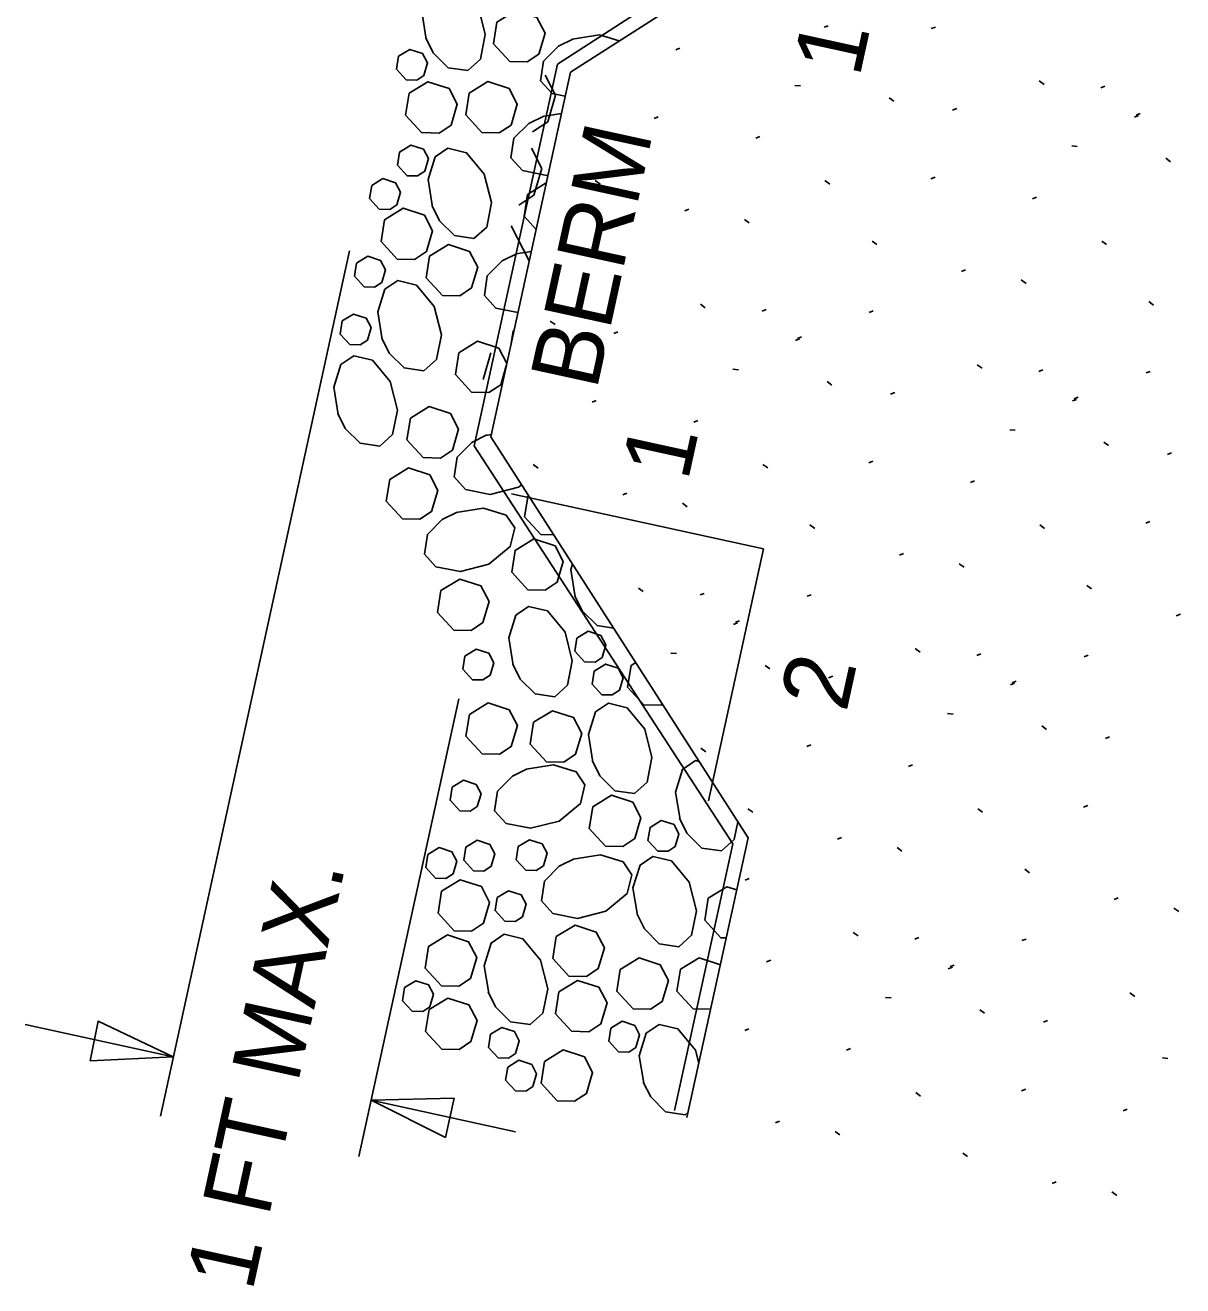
# Model space of a CAD drawing. Extents: x 2126110 to 2128246, y 1804858 to 1811658.
# Drawn here: x 2126534.8 to 2126619.6, y 1805336.1 to 1805428.3 of the extents above; entities that cross this region are included whole.
import ezdxf

# ---------------------------------------------------------------- set-up
doc = ezdxf.new("R2010")
doc.units = 0
doc.layers.add('1', color=7, linetype='Continuous')

msp = doc.modelspace()

# ---------------------------------------------------------------- linework, layer by layer
at = {"layer": '1'}
for p, q in [((2126573.804, 1805425.496), (2126651.738, 1805475.782)), ((2126574.757, 1805424.895), (2126652.954, 1805475.045)), ((2126593.323, 1805428.191), (2126593.622, 1805428.308)), ((2126601.172, 1805428.09), (2126601.47, 1805428.207)), ((2126582.473, 1805426.545), (2126582.771, 1805426.662)), ((2126595.778, 1805426.038), (2126596.076, 1805426.155)), ((2126595.915, 1805426.19), (2126596.213, 1805426.307)), ((2126567.699, 1805397.559), (2126573.804, 1805425.496)), ((2126574.757, 1805424.895), (2126568.927, 1805398.216)), ((2126572.902, 1805424.696), (2126573.665, 1805423.227)), ((2126609.429, 1805424.01), (2126609.077, 1805424.269)), ((2126573.665, 1805423.227), (2126573.087, 1805421.269)), ((2126591.189, 1805423.939), (2126591.589, 1805423.897)), ((2126613.586, 1805423.763), (2126613.884, 1805423.88)), ((2126598.434, 1805422.776), (2126598.082, 1805423.035)), ((2126572.713, 1805421.663), (2126574.101, 1805421.89)), ((2126580.884, 1805421.521), (2126581.182, 1805421.638)), ((2126602.736, 1805422.117), (2126603.034, 1805422.234)), ((2126616.04, 1805421.611), (2126616.339, 1805421.727)), ((2126616.177, 1805421.763), (2126616.476, 1805421.879)), ((2126573.087, 1805421.269), (2126571.976, 1805420.532)), ((2126588.32, 1805420.067), (2126588.618, 1805420.183)), ((2126611.451, 1805419.511), (2126611.851, 1805419.47)), ((2126571.898, 1805419.333), (2126572.661, 1805417.864)), ((2126618.697, 1805418.348), (2126618.344, 1805418.607)), ((2126572.661, 1805417.864), (2126572.082, 1805415.906)), ((2126576.923, 1805416.706), (2126576.57, 1805416.964)), ((2126593.74, 1805416.712), (2126593.387, 1805416.971)), ((2126601.146, 1805417.093), (2126601.444, 1805417.21)), ((2126572.082, 1805415.906), (2126570.972, 1805415.169)), ((2126608.583, 1805415.639), (2126608.881, 1805415.756)), ((2126583.123, 1805414.747), (2126583.421, 1805414.863)), ((2126587.846, 1805413.864), (2126587.493, 1805414.123)), ((2126570.403, 1805413.663), (2126571.74, 1805411.087)), ((2126597.185, 1805412.278), (2126596.833, 1805412.537)), ((2126614.002, 1805412.284), (2126613.65, 1805412.543)), ((2126558.575, 1805411.836), (2126544.731, 1805348.483)), ((2126570.763, 1805411.597), (2126571.892, 1805411.783)), ((2126576.369, 1805411.739), (2126576.667, 1805411.856)), ((2126603.385, 1805410.319), (2126603.684, 1805410.436)), ((2126608.108, 1805409.436), (2126607.756, 1805409.695)), ((2126584.626, 1805407.66), (2126584.274, 1805407.918)), ((2126588.783, 1805407.413), (2126589.081, 1805407.529)), ((2126617.448, 1805407.85), (2126617.095, 1805408.109)), ((2126573.631, 1805406.426), (2126573.279, 1805406.684)), ((2126596.631, 1805407.312), (2126596.929, 1805407.428)), ((2126577.933, 1805405.767), (2126578.231, 1805405.883)), ((2126591.237, 1805405.26), (2126591.536, 1805405.377)), ((2126591.374, 1805405.412), (2126591.673, 1805405.529)), ((2126568.932, 1805404.359), (2126568.354, 1805402.401)), ((2126586.648, 1805403.161), (2126587.048, 1805403.119)), ((2126604.889, 1805403.232), (2126604.536, 1805403.491)), ((2126609.045, 1805402.985), (2126609.344, 1805403.102)), ((2126616.894, 1805402.884), (2126617.192, 1805403.001)), ((2126593.894, 1805401.998), (2126593.541, 1805402.257)), ((2126598.195, 1805401.339), (2126598.493, 1805401.455)), ((2126611.637, 1805400.984), (2126611.935, 1805401.101)), ((2126576.343, 1805400.743), (2126576.641, 1805400.859)), ((2126611.5, 1805400.832), (2126611.798, 1805400.949)), ((2126583.78, 1805399.288), (2126584.078, 1805399.405)), ((2126568.547, 1805398.311), (2126568.963, 1805398.38)), ((2126606.911, 1805398.733), (2126607.311, 1805398.691)), ((2126586.642, 1805368.411), (2126567.699, 1805397.559)), ((2126568.927, 1805398.216), (2126587.758, 1805368.854)), ((2126614.156, 1805397.57), (2126613.804, 1805397.829)), ((2126596.606, 1805396.315), (2126596.904, 1805396.432)), ((2126618.458, 1805396.911), (2126618.756, 1805397.028)), ((2126572.382, 1805395.927), (2126572.03, 1805396.186)), ((2126589.199, 1805395.934), (2126588.847, 1805396.192)), ((2126604.042, 1805394.861), (2126604.341, 1805394.977)), ((2126570.435, 1805394.037), (2126588.886, 1805390.005)), ((2126578.582, 1805393.968), (2126578.881, 1805394.085)), ((2126583.305, 1805393.086), (2126582.953, 1805393.345)), ((2126616.868, 1805391.887), (2126617.167, 1805392.004)), ((2126573.536, 1805391.03), (2126572.584, 1805391.051)), ((2126592.645, 1805391.499), (2126592.292, 1805391.758)), ((2126609.462, 1805391.506), (2126609.11, 1805391.765)), ((2126588.886, 1805390.005), (2126584.857, 1805371.568)), ((2126598.845, 1805389.541), (2126599.143, 1805389.657)), ((2126603.568, 1805388.658), (2126603.215, 1805388.917)), ((2126612.907, 1805387.072), (2126612.555, 1805387.331)), ((2126580.086, 1805386.881), (2126579.733, 1805387.14)), ((2126584.242, 1805386.634), (2126584.541, 1805386.751)), ((2126592.091, 1805386.533), (2126592.389, 1805386.65)), ((2126586.697, 1805384.482), (2126586.995, 1805384.598)), ((2126586.834, 1805384.634), (2126587.132, 1805384.75)), ((2126619.107, 1805385.113), (2126619.406, 1805385.23)), ((2126600.349, 1805382.453), (2126599.996, 1805382.712)), ((2126582.108, 1805382.382), (2126582.508, 1805382.34)), ((2126604.505, 1805382.207), (2126604.803, 1805382.323)), ((2126612.353, 1805382.106), (2126612.652, 1805382.222)), ((2126589.353, 1805381.219), (2126589.001, 1805381.478)), ((2126593.655, 1805380.56), (2126593.953, 1805380.677)), ((2126606.96, 1805380.054), (2126607.258, 1805380.171)), ((2126607.096, 1805380.206), (2126607.395, 1805380.322)), ((2126566.577, 1805379.04), (2126559.253, 1805345.524)), ((2126602.37, 1805377.955), (2126602.77, 1805377.913)), ((2126609.616, 1805376.792), (2126609.263, 1805377.05)), ((2126613.917, 1805376.133), (2126614.216, 1805376.249)), ((2126584.659, 1805375.155), (2126584.306, 1805375.414)), ((2126592.065, 1805375.537), (2126592.363, 1805375.653)), ((2126599.502, 1805374.082), (2126599.8, 1805374.199)), ((2126588.104, 1805370.721), (2126587.752, 1805370.98)), ((2126604.922, 1805370.727), (2126604.569, 1805370.986)), ((2126612.328, 1805371.109), (2126612.626, 1805371.225)), ((2126583.282, 1805348.371), (2126587.758, 1805368.854)), ((2126594.304, 1805368.762), (2126594.603, 1805368.879)), ((2126582.374, 1805348.883), (2126586.642, 1805368.411)), ((2126599.027, 1805367.88), (2126598.675, 1805368.138)), ((2126608.367, 1805366.293), (2126608.014, 1805366.552)), ((2126587.55, 1805365.755), (2126587.848, 1805365.872)), ((2126614.567, 1805364.334), (2126614.865, 1805364.451)), ((2126619.29, 1805363.452), (2126618.937, 1805363.711)), ((2126586.159, 1805361.535), (2126585.771, 1805361.544)), ((2126595.808, 1805361.675), (2126595.456, 1805361.934)), ((2126599.964, 1805361.428), (2126600.263, 1805361.545)), ((2126607.813, 1805361.327), (2126608.111, 1805361.444)), ((2126589.114, 1805359.782), (2126589.413, 1805359.899)), ((2126602.556, 1805359.427), (2126602.854, 1805359.544)), ((2126602.419, 1805359.275), (2126602.717, 1805359.392)), ((2126597.83, 1805357.176), (2126598.23, 1805357.134)), ((2126616.071, 1805357.247), (2126615.718, 1805357.506)), ((2126605.075, 1805356.013), (2126604.723, 1805356.272)), ((2126534.837, 1805355.185), (2126545.678, 1805352.816)), ((2126609.377, 1805355.354), (2126609.675, 1805355.471)), ((2126587.525, 1805354.758), (2126587.823, 1805354.875)), ((2126594.961, 1805353.304), (2126595.26, 1805353.42)), ((2126618.093, 1805352.748), (2126618.492, 1805352.707)), ((2126607.787, 1805350.33), (2126608.086, 1805350.447)), ((2126560.155, 1805349.652), (2126570.729, 1805347.342)), ((2126600.381, 1805349.949), (2126600.029, 1805350.208)), ((2126615.224, 1805348.876), (2126615.522, 1805348.993)), ((2126589.764, 1805347.984), (2126590.062, 1805348.1)), ((2126594.487, 1805347.101), (2126594.134, 1805347.36)), ((2126603.826, 1805345.515), (2126603.474, 1805345.774)), ((2126610.027, 1805343.556), (2126610.325, 1805343.673)), ((2126614.749, 1805342.673), (2126614.397, 1805342.932))]:
    msp.add_line(p, q, dxfattribs=at)
for points in [[(2126564.199, 1805427.33), (2126563.871, 1805429.333), (2126564.387, 1805430.994), (2126565.328, 1805431.631), (2126566.696, 1805431.306), (2126567.99, 1805429.744), (2126568.522, 1805427.65), (2126568.164, 1805425.864), (2126567.234, 1805425.019), (2126565.796, 1805425.233), (2126564.706, 1805426.323), (2126564.168, 1805427.415)], [(2126570.308, 1805425.684), (2126569.122, 1805426.974), (2126569.375, 1805428.567), (2126570.748, 1805429.413), (2126572.302, 1805428.907), (2126572.898, 1805427.759), (2126572.446, 1805426.231), (2126571.578, 1805425.655), (2126570.309, 1805425.684)], [(2126574.376, 1805423.151), (2126573.417, 1805423.343), (2126572.571, 1805424.273), (2126572.786, 1805425.71), (2126573.875, 1805426.8), (2126574.968, 1805427.339)], [(2126574.883, 1805427.308), (2126576.886, 1805427.636), (2126578.331, 1805427.187)], [(2126562.736, 1805424.337), (2126562.024, 1805425.112), (2126562.176, 1805426.068), (2126563.001, 1805426.575), (2126563.932, 1805426.272), (2126564.29, 1805425.583), (2126564.019, 1805424.665), (2126563.498, 1805424.32), (2126562.736, 1805424.338)], [(2126563.875, 1805420.475), (2126562.688, 1805421.766), (2126562.942, 1805423.359), (2126564.315, 1805424.204), (2126565.869, 1805423.699), (2126566.465, 1805422.551), (2126566.013, 1805421.022), (2126565.145, 1805420.446), (2126563.875, 1805420.476)], [(2126568.273, 1805420.485), (2126567.086, 1805421.776), (2126567.341, 1805423.369), (2126568.713, 1805424.214), (2126570.267, 1805423.709), (2126570.863, 1805422.561), (2126570.411, 1805421.032), (2126569.543, 1805420.457), (2126568.273, 1805420.486)], [(2126573.111, 1805417.36), (2126573.032, 1805417.34), (2126571.247, 1805417.697), (2126570.401, 1805418.627), (2126570.616, 1805420.065), (2126571.705, 1805421.154), (2126572.797, 1805421.693)], [(2126562.806, 1805417.325), (2126562.094, 1805418.1), (2126562.246, 1805419.056), (2126563.071, 1805419.564), (2126564.002, 1805419.26), (2126564.36, 1805418.572), (2126564.089, 1805417.654), (2126563.568, 1805417.308), (2126562.806, 1805417.326)], [(2126564.658, 1805415.033), (2126564.33, 1805417.035), (2126564.846, 1805418.696), (2126565.787, 1805419.334), (2126567.155, 1805419.008), (2126568.449, 1805417.445), (2126568.98, 1805415.352), (2126568.623, 1805413.567), (2126567.693, 1805412.72), (2126566.255, 1805412.936), (2126565.166, 1805414.025), (2126564.627, 1805415.118)], [(2126560.761, 1805414.874), (2126560.05, 1805415.649), (2126560.202, 1805416.604), (2126561.026, 1805417.112), (2126561.958, 1805416.809), (2126562.315, 1805416.12), (2126562.044, 1805415.202), (2126561.524, 1805414.857), (2126560.762, 1805414.874)], [(2126572.243, 1805413.391), (2126571.358, 1805414.354), (2126571.612, 1805415.947), (2126572.985, 1805416.793), (2126572.987, 1805416.792)], [(2126562.076, 1805411.222), (2126560.89, 1805412.514), (2126561.143, 1805414.106), (2126562.516, 1805414.952), (2126564.07, 1805414.446), (2126564.666, 1805413.298), (2126564.214, 1805411.769), (2126563.346, 1805411.194), (2126562.076, 1805411.223)], [(2126565.378, 1805408.558), (2126564.192, 1805409.85), (2126564.446, 1805411.442), (2126565.819, 1805412.288), (2126567.373, 1805411.782), (2126567.969, 1805410.634), (2126567.516, 1805409.106), (2126566.648, 1805408.53), (2126565.379, 1805408.559)], [(2126559.659, 1805409.187), (2126558.947, 1805409.962), (2126559.099, 1805410.918), (2126559.923, 1805411.425), (2126560.855, 1805411.122), (2126561.213, 1805410.433), (2126560.942, 1805409.515), (2126560.421, 1805409.17), (2126559.659, 1805409.188)], [(2126570.914, 1805407.309), (2126569.297, 1805407.632), (2126568.452, 1805408.563), (2126568.667, 1805410), (2126569.756, 1805411.09), (2126570.848, 1805411.629)], [(2126560.98, 1805405.346), (2126560.652, 1805407.348), (2126561.168, 1805409.01), (2126562.109, 1805409.647), (2126563.477, 1805409.321), (2126564.772, 1805407.758), (2126565.303, 1805405.666), (2126564.945, 1805403.88), (2126564.015, 1805403.034), (2126562.578, 1805403.249), (2126561.488, 1805404.338), (2126560.949, 1805405.431)], [(2126558.605, 1805404.961), (2126557.894, 1805405.736), (2126558.046, 1805406.691), (2126558.87, 1805407.198), (2126559.802, 1805406.896), (2126560.16, 1805406.206), (2126559.889, 1805405.289), (2126559.367, 1805404.944), (2126558.606, 1805404.961)], [(2126570.421, 1805405.049), (2126570.566, 1805405.96), (2126570.628, 1805405.999)], [(2126567.514, 1805401.472), (2126566.328, 1805402.764), (2126566.582, 1805404.356), (2126567.955, 1805405.202), (2126569.509, 1805404.697), (2126570.096, 1805403.565)], [(2126557.76, 1805399.838), (2126557.432, 1805401.84), (2126557.948, 1805403.501), (2126558.889, 1805404.139), (2126560.257, 1805403.813), (2126561.552, 1805402.25), (2126562.083, 1805400.157), (2126561.725, 1805398.372), (2126560.795, 1805397.526), (2126559.358, 1805397.741), (2126558.268, 1805398.83), (2126557.729, 1805399.923)], [(2126570.059, 1805403.394), (2126569.653, 1805402.02), (2126568.784, 1805401.444), (2126567.514, 1805401.473)], [(2126563.971, 1805396.687), (2126562.786, 1805397.978), (2126563.039, 1805399.571), (2126564.412, 1805400.417), (2126565.966, 1805399.911), (2126566.562, 1805398.763), (2126566.11, 1805397.235), (2126565.242, 1805396.659), (2126563.972, 1805396.688)], [(2126571.181, 1805394.703), (2126570.96, 1805394.52), (2126568.866, 1805393.989), (2126567.081, 1805394.347), (2126566.235, 1805395.277), (2126566.45, 1805396.714), (2126567.539, 1805397.804), (2126568.632, 1805398.343)], [(2126562.454, 1805392.204), (2126561.267, 1805393.495), (2126561.522, 1805395.088), (2126562.894, 1805395.934), (2126564.448, 1805395.429), (2126565.044, 1805394.281), (2126564.592, 1805392.752), (2126563.724, 1805392.176), (2126562.454, 1805392.205)], [(2126572.584, 1805391.051), (2126571.397, 1805392.342), (2126571.651, 1805393.934), (2126571.667, 1805393.944)], [(2126566.377, 1805392.666), (2126568.379, 1805392.994), (2126570.041, 1805392.478), (2126570.678, 1805391.537), (2126570.352, 1805390.169), (2126568.79, 1805388.875), (2126566.696, 1805388.344), (2126564.911, 1805388.701), (2126564.065, 1805389.631), (2126564.28, 1805391.069), (2126565.368, 1805392.158), (2126566.461, 1805392.697)], [(2126571.638, 1805387.011), (2126570.452, 1805388.302), (2126570.706, 1805389.895), (2126572.078, 1805390.74), (2126573.632, 1805390.235), (2126574.228, 1805389.087), (2126573.777, 1805387.559), (2126572.909, 1805386.983), (2126571.639, 1805387.012)], [(2126575.107, 1805386.486), (2126574.779, 1805388.489), (2126574.906, 1805388.895)], [(2126566.208, 1805384.067), (2126565.022, 1805385.358), (2126565.276, 1805386.95), (2126566.649, 1805387.797), (2126568.203, 1805387.291), (2126568.798, 1805386.143), (2126568.347, 1805384.614), (2126567.479, 1805384.039), (2126566.208, 1805384.067)], [(2126577.911, 1805384.209), (2126576.705, 1805384.389), (2126575.615, 1805385.478), (2126575.076, 1805386.571)], [(2126570.566, 1805381.488), (2126570.238, 1805383.49), (2126570.754, 1805385.151), (2126571.695, 1805385.789), (2126573.063, 1805385.463), (2126574.357, 1805383.9), (2126574.888, 1805381.807), (2126574.531, 1805380.022), (2126573.601, 1805379.175), (2126572.163, 1805379.391), (2126571.074, 1805380.48), (2126570.535, 1805381.572)], [(2126575.793, 1805381.735), (2126575.081, 1805382.51), (2126575.234, 1805383.466), (2126576.057, 1805383.973), (2126576.99, 1805383.67), (2126577.347, 1805382.981), (2126577.076, 1805382.063), (2126576.556, 1805381.718), (2126575.793, 1805381.736)], [(2126567.584, 1805380.429), (2126566.872, 1805381.203), (2126567.024, 1805382.159), (2126567.848, 1805382.666), (2126568.78, 1805382.363), (2126569.138, 1805381.675), (2126568.867, 1805380.757), (2126568.346, 1805380.411), (2126567.584, 1805380.429)], [(2126580.124, 1805378.59), (2126578.938, 1805379.882), (2126579.192, 1805381.474), (2126579.53, 1805381.683)], [(2126577.058, 1805379.329), (2126576.346, 1805380.104), (2126576.499, 1805381.059), (2126577.322, 1805381.567), (2126578.255, 1805381.264), (2126578.613, 1805380.575), (2126578.342, 1805379.657), (2126577.821, 1805379.312), (2126577.059, 1805379.33)], [(2126568.285, 1805374.996), (2126567.099, 1805376.287), (2126567.353, 1805377.879), (2126568.725, 1805378.725), (2126570.28, 1805378.22), (2126570.876, 1805377.072), (2126570.423, 1805375.543), (2126569.555, 1805374.967), (2126568.286, 1805374.996)], [(2126572.991, 1805374.426), (2126571.805, 1805375.718), (2126572.06, 1805377.311), (2126573.432, 1805378.156), (2126574.986, 1805377.651), (2126575.582, 1805376.503), (2126575.13, 1805374.974), (2126574.262, 1805374.398), (2126572.992, 1805374.427)], [(2126576.4, 1805374.403), (2126576.073, 1805376.406), (2126576.589, 1805378.067), (2126577.53, 1805378.704), (2126578.898, 1805378.378), (2126580.192, 1805376.816), (2126580.723, 1805374.723), (2126580.366, 1805372.937), (2126579.436, 1805372.091), (2126577.998, 1805372.306), (2126576.909, 1805373.395), (2126576.37, 1805374.488)], [(2126581.491, 1805378.626), (2126581.394, 1805378.562), (2126580.125, 1805378.591)], [(2126582.778, 1805370.202), (2126582.451, 1805372.204), (2126582.966, 1805373.865), (2126583.907, 1805374.503), (2126584.177, 1805374.439)], [(2126571.512, 1805373.872), (2126573.514, 1805374.201), (2126575.175, 1805373.684), (2126575.813, 1805372.743), (2126575.487, 1805371.375), (2126573.924, 1805370.081), (2126571.831, 1805369.55), (2126570.046, 1805369.907), (2126569.2, 1805370.837), (2126569.415, 1805372.275), (2126570.504, 1805373.364), (2126571.597, 1805373.903)], [(2126566.654, 1805370.831), (2126565.942, 1805371.605), (2126566.095, 1805372.561), (2126566.919, 1805373.068), (2126567.85, 1805372.765), (2126568.208, 1805372.076), (2126567.937, 1805371.159), (2126567.416, 1805370.813), (2126566.654, 1805370.83)], [(2126577.32, 1805368.249), (2126576.133, 1805369.541), (2126576.388, 1805371.134), (2126577.76, 1805371.979), (2126579.314, 1805371.474), (2126579.91, 1805370.326), (2126579.458, 1805368.797), (2126578.59, 1805368.221), (2126577.32, 1805368.251)], [(2126581.141, 1805367.885), (2126580.429, 1805368.66), (2126580.582, 1805369.615), (2126581.405, 1805370.122), (2126582.338, 1805369.82), (2126582.696, 1805369.13), (2126582.425, 1805368.213), (2126581.903, 1805367.868), (2126581.142, 1805367.885)], [(2126587.003, 1805370.032), (2126586.743, 1805368.736), (2126585.813, 1805367.89), (2126584.376, 1805368.104), (2126583.286, 1805369.194), (2126582.747, 1805370.287)], [(2126564.875, 1805365.898), (2126564.164, 1805366.673), (2126564.316, 1805367.629), (2126565.14, 1805368.136), (2126566.072, 1805367.833), (2126566.43, 1805367.144), (2126566.159, 1805366.227), (2126565.638, 1805365.881), (2126564.876, 1805365.898)], [(2126567.659, 1805366.443), (2126566.948, 1805367.217), (2126567.1, 1805368.173), (2126567.924, 1805368.68), (2126568.856, 1805368.377), (2126569.214, 1805367.688), (2126568.943, 1805366.771), (2126568.422, 1805366.425), (2126567.66, 1805366.442)], [(2126571.491, 1805366.476), (2126570.779, 1805367.251), (2126570.931, 1805368.207), (2126571.756, 1805368.714), (2126572.687, 1805368.411), (2126573.045, 1805367.722), (2126572.774, 1805366.805), (2126572.253, 1805366.459), (2126571.492, 1805366.477)], [(2126574.942, 1805367.282), (2126576.945, 1805367.61), (2126578.606, 1805367.094), (2126579.244, 1805366.153), (2126578.918, 1805364.785), (2126577.355, 1805363.49), (2126575.262, 1805362.96), (2126573.477, 1805363.317), (2126572.63, 1805364.247), (2126572.846, 1805365.685), (2126573.934, 1805366.774), (2126575.027, 1805367.313)], [(2126579.661, 1805363.19), (2126579.333, 1805365.193), (2126579.849, 1805366.854), (2126580.79, 1805367.491), (2126582.158, 1805367.166), (2126583.453, 1805365.603), (2126583.984, 1805363.51), (2126583.626, 1805361.724), (2126582.696, 1805360.878), (2126581.259, 1805361.093), (2126580.169, 1805362.182), (2126579.63, 1805363.275)], [(2126566.248, 1805362.054), (2126565.061, 1805363.345), (2126565.315, 1805364.938), (2126566.688, 1805365.784), (2126568.242, 1805365.279), (2126568.838, 1805364.13), (2126568.386, 1805362.602), (2126567.517, 1805362.026), (2126566.248, 1805362.055)], [(2126585.77, 1805361.543), (2126584.584, 1805362.834), (2126584.838, 1805364.427), (2126586.21, 1805365.272), (2126586.925, 1805365.04)], [(2126569.95, 1805362.747), (2126569.238, 1805363.522), (2126569.39, 1805364.478), (2126570.214, 1805364.985), (2126571.147, 1805364.682), (2126571.505, 1805363.993), (2126571.233, 1805363.075), (2126570.712, 1805362.73), (2126569.95, 1805362.748)], [(2126574.648, 1805358.735), (2126573.461, 1805360.026), (2126573.715, 1805361.619), (2126575.088, 1805362.465), (2126576.642, 1805361.959), (2126577.238, 1805360.81), (2126576.786, 1805359.283), (2126575.918, 1805358.707), (2126574.648, 1805358.736)], [(2126565.302, 1805358.015), (2126564.116, 1805359.306), (2126564.37, 1805360.899), (2126565.742, 1805361.744), (2126567.296, 1805361.239), (2126567.892, 1805360.091), (2126567.441, 1805358.562), (2126566.573, 1805357.987), (2126565.303, 1805358.015)], [(2126568.771, 1805357.49), (2126568.443, 1805359.493), (2126568.96, 1805361.153), (2126569.9, 1805361.791), (2126571.269, 1805361.465), (2126572.563, 1805359.903), (2126573.094, 1805357.809), (2126572.737, 1805356.024), (2126571.806, 1805355.178), (2126570.369, 1805355.393), (2126569.279, 1805356.482), (2126568.74, 1805357.574)], [(2126579.337, 1805356.334), (2126578.15, 1805357.626), (2126578.405, 1805359.218), (2126579.777, 1805360.064), (2126581.331, 1805359.558), (2126581.927, 1805358.41), (2126581.475, 1805356.882), (2126580.607, 1805356.306), (2126579.337, 1805356.335)], [(2126583.735, 1805356.345), (2126582.548, 1805357.636), (2126582.803, 1805359.228), (2126584.175, 1805360.074), (2126585.729, 1805359.568), (2126585.729, 1805359.568)], [(2126563.174, 1805356.157), (2126562.462, 1805356.932), (2126562.614, 1805357.888), (2126563.438, 1805358.395), (2126564.371, 1805358.092), (2126564.728, 1805357.403), (2126564.457, 1805356.486), (2126563.936, 1805356.141), (2126563.174, 1805356.158)], [(2126574.84, 1805354.689), (2126573.655, 1805355.981), (2126573.908, 1805357.574), (2126575.281, 1805358.419), (2126576.835, 1805357.914), (2126577.431, 1805356.766), (2126576.979, 1805355.237), (2126576.111, 1805354.661), (2126574.841, 1805354.691)], [(2126565.333, 1805353.393), (2126564.146, 1805354.684), (2126564.401, 1805356.277), (2126565.773, 1805357.122), (2126567.327, 1805356.617), (2126567.923, 1805355.469), (2126567.472, 1805353.941), (2126566.603, 1805353.365), (2126565.334, 1805353.394)], [(2126585.021, 1805356.327), (2126585.005, 1805356.316), (2126583.735, 1805356.345)], [(2126569.457, 1805352.739), (2126568.745, 1805353.514), (2126568.898, 1805354.469), (2126569.721, 1805354.976), (2126570.654, 1805354.674), (2126571.011, 1805353.984), (2126570.74, 1805353.067), (2126570.219, 1805352.722), (2126569.457, 1805352.74)], [(2126578.268, 1805353.185), (2126577.557, 1805353.96), (2126577.709, 1805354.915), (2126578.533, 1805355.423), (2126579.464, 1805355.12), (2126579.822, 1805354.431), (2126579.551, 1805353.513), (2126579.03, 1805353.168), (2126578.269, 1805353.185)], [(2126580.12, 1805350.892), (2126579.792, 1805352.895), (2126580.309, 1805354.556), (2126581.249, 1805355.193), (2126582.617, 1805354.868), (2126583.911, 1805353.305), (2126584.153, 1805352.354)], [(2126573.787, 1805349.594), (2126572.602, 1805350.885), (2126572.855, 1805352.478), (2126574.228, 1805353.324), (2126575.782, 1805352.818), (2126576.378, 1805351.67), (2126575.926, 1805350.141), (2126575.058, 1805349.566), (2126573.788, 1805349.595)], [(2126570.722, 1805350.333), (2126570.01, 1805351.108), (2126570.163, 1805352.063), (2126570.986, 1805352.57), (2126571.919, 1805352.268), (2126572.276, 1805351.578), (2126572.005, 1805350.661), (2126571.485, 1805350.316), (2126570.722, 1805350.333)], [(2126583.371, 1805348.776), (2126583.155, 1805348.58), (2126581.717, 1805348.795), (2126580.628, 1805349.885), (2126580.089, 1805350.977)]]:
    msp.add_lwpolyline(points, dxfattribs=at)
for points in [[(2126539.596, 1805352.538), (2126545.678, 1805352.816), (2126540.181, 1805355.433)], [(2126566.242, 1805349.802), (2126560.155, 1805349.652), (2126565.596, 1805346.92)]]:
    msp.add_lwpolyline(points, close=True, dxfattribs=at)

# ---------------------------------------------------------------- texts
for s, p in [('1', (2126595.905, 1805424.435)), ('BERM', (2126576.663, 1805401.544)), ('1', (2126583.345, 1805394.877)), ('2', (2126594.949, 1805377.967)), ('1 FT MAX.', (2126551.462, 1805335.563))]:
    msp.add_text(s, height=5, rotation=77.67359, dxfattribs=at).set_placement(p)

doc.saveas('drawing.dxf')
